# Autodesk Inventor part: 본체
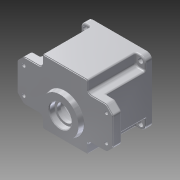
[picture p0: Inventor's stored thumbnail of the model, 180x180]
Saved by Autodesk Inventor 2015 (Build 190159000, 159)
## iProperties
Created: 2016-02
Part Number: 본체
Material: Aluminum 6061
Document SubType Name: Modeling
Designer: Administrator
Density: 2.7 g/cm^3
Appearance: Aluminum - Flat
Mass: 874.229 g
Surface Area: 763.22 cm^2
Volume: 323.788 cm^3
Author: Administrator
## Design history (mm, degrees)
sketch "Sketch1"
  geometry: L1 (-70, 30)-(-70, -30); L2 (70, -30)-(70, 30); L3 (33, 47)-(-33, 47); L4 (-33, -47)-(33, -47); L5 (70, 30)-(33, 30); L6 (-33, 30)-(-70, 30); L7 (33, -47)-(33, -30); L8 (33, 30)-(33, 47); L9 (-70, -30)-(-33, -30); L10 (33, -30)-(70, -30); L11 (-33, 47)-(-33, 30); L12 (-33, -30)-(-33, -47); 1 further point
  constraints: 24 end point, 10 parallel, 4 perpendicular, 3 collinear, 3 horizontal
  dimensions: "d0" = 140 distance between parallel lines of L1 L2; "d1" = 70 distance from line of point (0, 0) L2; "d2" = 94 distance between parallel lines of L4 L3; "d3" = 47 distance from line of L3 point (0, 0); "d4" = 66 distance between parallel lines of L11 L8; "d5" = 66 distance between parallel lines of L12 L7; "d6" = 33 distance from line of point (0, 0) L7; "d7" = 60 distance of L2.start L2.end; "d8" = 30 distance from line of point (0, 0) L5
extrude "Extrusion1" new body sketch "Sketch1" distance "d9" = 13; taper "d10" = 0 deg
sketch "Sketch2"
  geometry: L1 (-70, 30)-(-70, -30) reference; L2 (-70, -30)-(-33, -30) reference; L3 (-33, -30)-(-33, -47) reference; L4 (-33, -47)-(33, -47) reference; L5 (33, -47)-(33, -30) reference; L6 (33, -30)-(70, -30) reference; L7 (70, -30)-(70, 30) reference; L8 (70, 30)-(33, 30) reference; L9 (33, 30)-(33, 47) reference; L10 (33, 47)-(-33, 47) reference; L11 (-33, 47)-(-33, 30) reference; L12 (-33, 30)-(-70, 30) reference; L13 (47, 47)-(-47, 47); L14 (-47, 47)-(-47, -47); L15 (-47, -47)-(47, -47); L16 (47, -47)-(47, 47); L17 (47, 47)-(-47, -47); L18 (-47, 47)-(47, -47); 1 further point
  constraints: 12 end point, 2 midpoint, 2 parallel, 1 horizontal, 1 perpendicular
  dimensions: "d11" = 94 distance of L15.end L14.end; "d12" = 94 distance of L14.end L13.end
extrude "Extrusion2" join sketch "Sketch2" distance "d13" = 67; taper "d14" = 0 deg
sketch "Sketch4"
  geometry: L1 (-70, 30)-(-70, -30) reference; L2 (-70, -30)-(-33, -30) reference; L3 (-33, -30)-(-33, -47) reference; L4 (-33, -47)-(33, -47) reference; L5 (33, -47)-(33, -30) reference; L6 (33, -30)-(70, -30) reference; L7 (70, -30)-(70, 30) reference; L8 (70, 30)-(33, 30) reference; L9 (33, 30)-(33, 47) reference; L10 (33, 47)-(-33, 47) reference; L11 (-33, 47)-(-33, 30) reference; L12 (-33, 30)-(-70, 30) reference; L13 (-33, 30)-(-33, 47) reference; L14 (-47, 47)-(-33, 47) reference; L15 (-47, 30)-(-47, 47) reference; L16 (-47, 30)-(-33, 30) reference; L17 (33, 47)-(33, 30) reference; L18 (33, 30)-(47, 30) reference; L19 (47, 47)-(47, 30) reference; L20 (33, 47)-(47, 47) reference; L21 (47, -30)-(33, -30) reference; L22 (33, -30)-(33, -47) reference; L23 (47, -47)-(33, -47) reference; L24 (47, -30)-(47, -47) reference; L25 (-33, -30)-(-47, -30) reference; L26 (-47, -47)-(-47, -30) reference; L27 (-33, -47)-(-47, -47) reference; L28 (-33, -47)-(-33, -30) reference; 1 further point
extrude "Extrusion4" cut sketch "Sketch4" distance "d17" = 57; taper "d18" = 0 deg
sketch "Sketch5"
  geometry: L1 (-33, 47)-(-33, 30) reference; L2 (-47, 47)-(-33, 47) reference; L3 (-47, 30)-(-47, 47) reference; L4 (-33, 30)-(-47, 30) reference; L5 (33, 30)-(33, 47) reference; L6 (47, 30)-(33, 30) reference; L7 (47, 47)-(47, 30) reference; L8 (33, 47)-(47, 47) reference; L9 (33, -30)-(47, -30) reference; L10 (33, -47)-(33, -30) reference; L11 (47, -47)-(33, -47) reference; L12 (47, -30)-(47, -47) reference; L13 (-47, -30)-(-33, -30) reference; L14 (-47, -47)-(-47, -30) reference; L15 (-33, -47)-(-47, -47) reference; L16 (-33, -30)-(-33, -47) reference; L17 (-40, -40)-(40, -40); L18 (40, -40)-(40, 40); L19 (40, 40)-(-40, 40); L20 (-40, 40)-(-40, -40); L21 (-40, -40)-(40, 40); L22 (40, -40)-(-40, 40); 5 further points
  constraints: 12 end point, 4 coincident, 2 midpoint, 2 parallel, 1 horizontal, 1 perpendicular
  dimensions: "d20" = 80 distance of L19.end L18.end; "d21" = 80 distance of L18.end L17.end
hole "Hole1" sketch "Sketch5" at (-40, 40), (40, 40), (-40, -40), (40, -40) diameter "d22" = 7; stored, may be unused: countersink angle "d26" = 90 deg, drill point angle "d28" = 118 deg; dims "d23" = 6, "d24" = 4, "d25" = 2, "d27" = 8
fillet "Fillet1" dims "d29" = 8
sketch "Sketch6"
  geometry: C1 r 43 at (0, 0); 1 further point
  constraints: 1 centre point, 1 coincident
  dimensions: "d30" = 86 diameter of C1
extrude "Extrusion5" cut sketch "Sketch6" distance "d31" = 9; taper "d32" = 0 deg
sketch "Sketch7"
  geometry: C1 r 40 at (0, 0); 1 further point
  constraints: 1 centre point, 1 coincident
  dimensions: "d33" = 80 diameter of C1
extrude "Extrusion6" cut sketch "Sketch7" distance "d34" = 62; taper "d35" = 0 deg
sketch "Sketch8"
  geometry: A1 r 40 centre (0, 0) between (39.148, -8.214) and (39.148, 8.214) reference; A2 r 36 centre (0, 0) between (36, 0) and (35.778, -3.995); A3 r 4 centre (36, 0) between (35.852, 3.997) and (35.852, -3.997); A4 r 3.5 centre (35.722, 7.495) between (35.778, 3.995) and (39.148, 8.214); A5 r 3.5 centre (35.722, -7.495) between (39.148, -8.214) and (35.778, -3.995); A6 r 40 centre (0, 0) between (39.148, -8.214) and (39.148, 8.214); 1 further point
  constraints: 15 point on circle, 5 centre point, 5 tangent, 2 coincident, 1 horizontal alignment
  dimensions: "d36" = 72 diameter of A2; "d37" = 8 diameter of A3; "d38" = 7 diameter of A4; "d39" = 7 diameter of A5
extrude "Extrusion7" join sketch "Sketch8" distance "d40" = 62; taper "d41" = 0 deg
hole "Hole2" diameter "d44" = 3.242; stored, may be unused: countersink angle "d48" = 90 deg, drill point angle "d50" = 118 deg; dims "d42" = 10, "d43" = 10, "d45" = 7, "d46" = 4, "d47" = 2, "d49" = 9
mirror "Mirror1"
sketch "Sketch9"
  geometry: A1 r 3.5 centre (-35.722, -7.495) between (-35.852, -3.997) and (-39.148, -8.214) reference; A2 r 40 centre (0, 0) between (-39.148, -8.214) and (39.148, -8.214) reference; A3 r 3.5 centre (35.722, -7.495) between (39.148, -8.214) and (35.852, -3.997) reference; A4 r 4 centre (36, 0) between (35.852, 3.997) and (35.852, -3.997) reference; A5 r 3.5 centre (35.722, 7.495) between (35.852, 3.997) and (39.148, 8.214) reference; A6 r 40 centre (0, 0) between (39.148, 8.214) and (-39.148, 8.214) reference; A7 r 3.5 centre (-35.722, 7.495) between (-39.148, 8.214) and (-35.852, 3.997) reference; A8 r 4 centre (-36, 0) between (-35.852, -3.997) and (-35.852, 3.997) reference; A9 r 21 centre (0, 11) between (8.978, -7.984) and (-8.978, -7.984); A10 r 15 centre (0, -20) between (-8.978, -7.984) and (8.978, -7.984); 1 further point
  constraints: 4 point on circle, 2 centre point, 2 vertical alignment
  dimensions: "d51" = 42 diameter of A9; "d52" = 11 distance of point (0, 0) A9.centre; "d53" = 30 diameter of A10; "d54" = 20 distance of point (0, 0) A10.centre
extrude "Extrusion8" join sketch "Sketch9" distance "d55" = 7; taper "d56" = 0 deg
hole "Hole3" diameter "d59" = 19; stored, may be unused: countersink angle "d63" = 90 deg, drill point angle "d65" = 0 deg; dims "d57" = 10, "d58" = 10, "d60" = 7, "d61" = 22, "d62" = 7, "d64" = 8
sketch "Sketch10"
  geometry: C1 r 28 at (0, -11); A1 r 21 centre (0, -11) between (-8.978, 7.984) and (8.978, 7.984) reference; 1 further point
  constraints: 1 centre point, 1 coincident
  dimensions: "d66" = 56 diameter of C1
extrude "Extrusion9" join sketch "Sketch10" distance "d67" = 7; taper "d68" = -10 deg
hole "Hole4" diameter "d71" = 25; stored, may be unused: countersink angle "d75" = 90 deg, drill point angle "d77" = 0 deg; dims "d69" = 10, "d70" = 10, "d72" = 7, "d73" = 32, "d74" = 8, "d76" = 13
sketch "Sketch11"
  geometry: C1 r 11 at (0, -20) reference; C2 r 17.5 at (0, 11); A1 r 15 centre (0, -20) between (-8.978, -7.984) and (8.978, -7.984) reference; A2 r 21 centre (0, 11) between (8.978, -7.984) and (-8.978, -7.984) reference; 1 further point
  constraints: 1 centre point, 1 coincident
  dimensions: "d78" = 35 diameter of C2
extrude "Extrusion10" cut sketch "Sketch11" distance "d79" = 10; taper "d80" = 0 deg
fillet "Fillet2" dims "d81" = 0.3
fillet "Fillet3" dims "d82" = 2
chamfer "Chamfer1" distance "d83" = 10; stored, may be unused: second distance "d84" = 2, angle "d85" = 45 deg
chamfer "Chamfer2" distance "d86" = 10; stored, may be unused: second distance "d87" = 2, angle "d88" = 45 deg
sketch "Sketch13"
  geometry: L1 (70, -20)-(60, -30) reference; L2 (70, -20)-(70, 20) reference; L3 (60, 30)-(70, 20) reference; L4 (60, 30)-(33, 30) reference; L5 (33, 30)-(33, 47) reference; L6 (33, 47)-(-33, 47) reference; L7 (-33, 47)-(-33, 30) reference; L8 (-33, 30)-(-60, 30) reference; L9 (-70, 20)-(-60, 30) reference; L10 (-70, 20)-(-70, -20) reference; L11 (-60, -30)-(-70, -20) reference; L12 (-60, -30)-(-33, -30) reference; L13 (-33, -30)-(-33, -47) reference; L14 (-33, -47)-(33, -47) reference; L15 (33, -47)-(33, -30) reference; L16 (33, -30)-(60, -30) reference; L17 (32, -46)-(-32, -46); L18 (-32, -46)-(-32, -29); L19 (-32, -29)-(-59.586, -29); L20 (-59.586, -29)-(-69, -19.586); L21 (-69, -19.586)-(-69, 19.586); L22 (-69, 19.586)-(-59.586, 29); L23 (-59.586, 29)-(-32, 29); L24 (-32, 29)-(-32, 46); L25 (-32, 46)-(32, 46); L26 (32, 46)-(32, 29); L27 (32, 29)-(59.586, 29); L28 (59.586, 29)-(69, 19.586); L29 (69, 19.586)-(69, -19.586); L30 (69, -19.586)-(59.586, -29); L31 (59.586, -29)-(32, -29); L32 (32, -29)-(32, -46); C1 r 28 at (0, -11) reference; A1 r 4 centre (36, 0) between (35.852, 3.997) and (35.852, -3.997) reference; 1 further point
  constraints: 32 end point, 15 other
  dimensions: "d89" = 1 distance between parallel lines of L14 L17
extrude "Extrusion11" cut sketch "Sketch13" distance "d90" = 1; taper "d91" = 0 deg
sketch "Sketch14"
  geometry: L1 (-60, 19)-(60, 19); L2 (60, 19)-(60, -19); L3 (60, -19)-(-60, -19); L4 (-60, -19)-(-60, 19); L5 (-60, 19)-(60, -19); L6 (60, 19)-(-60, -19); 5 further points
  constraints: 12 end point, 4 coincident, 2 midpoint, 2 parallel, 1 horizontal, 1 perpendicular
  dimensions: "d92" = 120 distance of L2.end L3.end; "d93" = 38 distance of L1.end L2.end
hole "Hole5" sketch "Sketch14" at (-60, 19), (60, 19), (60, -19), (-60, -19) diameter "d94" = 5; stored, may be unused: countersink angle "d98" = 90 deg, drill point angle "d100" = 0 deg; dims "d95" = 7, "d96" = 9, "d97" = 4, "d99" = 13
sketch "Sketch15"
  geometry: L1 (0, 0)-(78, 0) reference; 2 further points
  constraints: 1 vertical alignment, 1 other
  dimensions: "d101" = 40 distance from line of point (39, -40) L1
emboss "Emboss1" sketch "Sketch15" dims "d102" = 0.5, "d103" = 0
fillet "Fillet4" dims "d104" = 2
fillet "Fillet5" dims "d105" = 2
fillet "Fillet6" dims "d106" = 2
fillet "Fillet7" dims "d107" = 3
fillet "Fillet8" dims "d108" = 2
chamfer "Chamfer3" distance "d109" = 1; stored, may be unused: second distance "d110" = 2, angle "d111" = 45 deg
fillet "Fillet9" dims "d112" = 5
fillet "Fillet10" dims "d113" = 4
fillet "Fillet11" dims "d114" = 5
fillet "Fillet12" dims "d115" = 6
fillet "Fillet13" dims "d116" = 0.3
fillet "Fillet14" dims "d117" = 0.3
body "Solid1"
node "Projected Loop1"
node "Projected Loop6"
node "Projected Loop7"
node "Projected Loop8"
node "Projected Loop9"
node "Projected Loop10"
node "Projected Loop11"
node "Projected Loop12"
node "Projected Loop13"
node "Projected Loop14"
node "Projected Loop15"
node "Projected Loop16"
node "Projected Loop17"
node "Projected Loop18"
